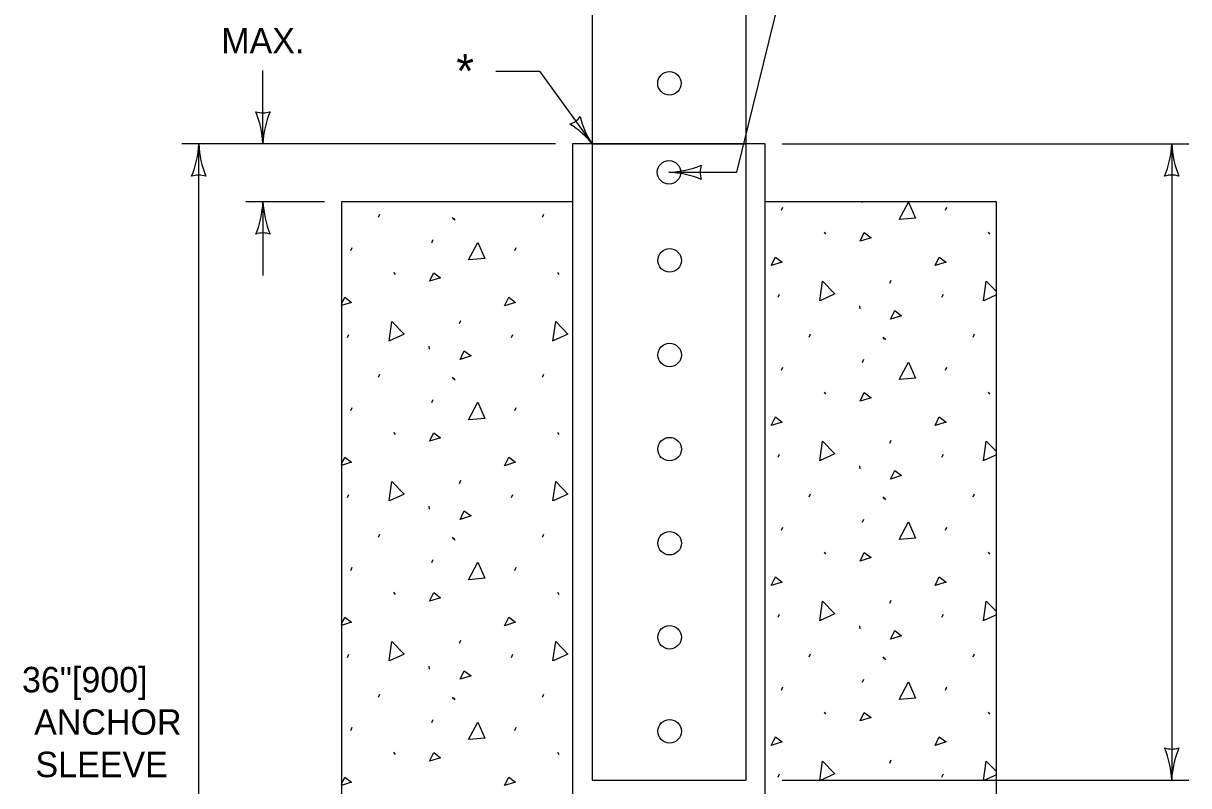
# Model space of a CAD drawing. Extents: x 49940 to 50043, y 49986 to 50011.
# Drawn here: x 50011.713 to 50014.462, y 49993.98 to 49995.777 of the extents above; entities that cross this region are included whole.
import ezdxf

# ---------------------------------------------------------------- set-up
doc = ezdxf.new("R2010")
doc.units = 0
for name, color, linetype in [('Level 1', 7, 'Continuous'), ('Level 2', 7, 'Continuous'), ('Level 3', 7, 'Continuous'), ('Level 4', 7, 'Continuous')]:
    doc.layers.add(name, color=color, linetype=linetype)

msp = doc.modelspace()

# ---------------------------------------------------------------- linework, layer by layer
at = {"layer": 'Level 1'}
for p, q in [((50013.4632, 49995.4928), (50013.0088, 49995.4928)), ((50013.0088, 49995.4928), (50013.0088, 49992.7712)), ((50013.4632, 49992.7712), (50013.4632, 49995.4928)), ((50013.0088, 49995.3565), (50012.4634, 49995.3565)), ((50012.4634, 49995.3565), (50012.4634, 49992.6303)), ((50014.0084, 49995.3565), (50013.4632, 49995.3565)), ((50013.6927, 49995.355), (50013.6934, 49995.3565)), ((50014.0084, 49992.6303), (50014.0084, 49995.3565)), ((50012.5512, 49995.3201), (50012.5544, 49995.3273)), ((50012.9377, 49995.3201), (50012.941, 49995.3273)), ((50013.5014, 49995.3365), (50013.5047, 49995.3437)), ((50013.888, 49995.3365), (50013.8912, 49995.3437)), ((50012.7247, 49995.3201), (50012.728, 49995.3151)), ((50012.728, 49995.3182), (50012.7313, 49995.3134)), ((50013.6024, 49995.2848), (50013.6055, 49995.28)), ((50013.9889, 49995.2848), (50013.992, 49995.28)), ((50012.4858, 49995.2416), (50012.4889, 49995.2489)), ((50012.677, 49995.2602), (50012.6802, 49995.2675)), ((50012.8724, 49995.2416), (50012.8756, 49995.2489)), ((50012.5866, 49995.1901), (50012.5899, 49995.1852)), ((50012.9732, 49995.1901), (50012.9764, 49995.1852)), ((50013.7573, 49995.1647), (50013.7605, 49995.1718)), ((50013.4934, 49995.1314), (50013.4966, 49995.1388)), ((50013.88, 49995.1314), (50013.8832, 49995.1388)), ((50013.6853, 49995.1112), (50013.686, 49995.104)), ((50012.7416, 49995.0697), (50012.7449, 49995.0771)), ((50012.4778, 49995.0366), (50012.481, 49995.044)), ((50012.8643, 49995.0366), (50012.8674, 49995.044)), ((50013.5668, 49995.0378), (50013.5701, 49995.0451)), ((50013.7404, 49995.0378), (50013.7435, 49995.0331)), ((50013.7435, 49995.036), (50013.7468, 49995.0311)), ((50013.9535, 49995.0378), (50013.9565, 49995.0451)), ((50012.6696, 49995.0164), (50012.6704, 49995.009)), ((50013.6927, 49994.9781), (50013.696, 49994.9853)), ((50012.5512, 49994.9431), (50012.5544, 49994.9504)), ((50012.7247, 49994.9431), (50012.728, 49994.9382)), ((50012.728, 49994.9411), (50012.7313, 49994.9364)), ((50012.9377, 49994.9431), (50012.941, 49994.9504)), ((50013.5014, 49994.9595), (50013.5047, 49994.9667)), ((50013.888, 49994.9595), (50013.8912, 49994.9667)), ((50012.677, 49994.8833), (50012.6802, 49994.8906)), ((50013.6024, 49994.9079), (50013.6055, 49994.903)), ((50013.9889, 49994.9079), (50013.992, 49994.903)), ((50012.4858, 49994.8648), (50012.4889, 49994.872)), ((50012.8724, 49994.8648), (50012.8756, 49994.872)), ((50012.5866, 49994.8131), (50012.5899, 49994.8082)), ((50012.9732, 49994.8131), (50012.9764, 49994.8082)), ((50013.7573, 49994.7876), (50013.7605, 49994.7948)), ((50013.4934, 49994.7545), (50013.4966, 49994.7617)), ((50013.88, 49994.7545), (50013.8832, 49994.7617)), ((50013.6853, 49994.7342), (50013.686, 49994.727)), ((50012.7416, 49994.6928), (50012.7449, 49994.7001)), ((50012.4778, 49994.6597), (50012.481, 49994.6669)), ((50012.8643, 49994.6597), (50012.8674, 49994.6669)), ((50013.5668, 49994.6609), (50013.5701, 49994.6681)), ((50013.9535, 49994.6609), (50013.9565, 49994.6681)), ((50012.6696, 49994.6395), (50012.6704, 49994.6322)), ((50013.7404, 49994.6609), (50013.7435, 49994.6561)), ((50013.7435, 49994.6591), (50013.7468, 49994.6543)), ((50013.5014, 49994.5826), (50013.5047, 49994.5898)), ((50013.6927, 49994.6011), (50013.696, 49994.6084)), ((50013.888, 49994.5826), (50013.8912, 49994.5898)), ((50012.5512, 49994.5661), (50012.5544, 49994.5733)), ((50012.7247, 49994.5661), (50012.728, 49994.5614)), ((50012.728, 49994.5643), (50012.7313, 49994.5594)), ((50012.9377, 49994.5661), (50012.941, 49994.5733)), ((50013.6024, 49994.531), (50013.6055, 49994.5261)), ((50013.9889, 49994.531), (50013.992, 49994.5261)), ((50012.677, 49994.5063), (50012.6802, 49994.5136)), ((50012.4858, 49994.4878), (50012.4889, 49994.495)), ((50012.8724, 49994.4878), (50012.8756, 49994.495)), ((50012.5866, 49994.4361), (50012.5899, 49994.4311)), ((50012.9732, 49994.4361), (50012.9764, 49994.4311)), ((50013.7573, 49994.4106), (50013.7605, 49994.4179)), ((50013.4934, 49994.3776), (50013.4966, 49994.3848)), ((50013.88, 49994.3776), (50013.8832, 49994.3848)), ((50013.6853, 49994.3573), (50013.686, 49994.3501)), ((50012.7416, 49994.3159), (50012.7449, 49994.3231)), ((50012.4778, 49994.2827), (50012.481, 49994.29)), ((50012.8643, 49994.2827), (50012.8674, 49994.29)), ((50013.5668, 49994.2839), (50013.5701, 49994.2912)), ((50013.7404, 49994.2839), (50013.7435, 49994.2791)), ((50013.7435, 49994.2821), (50013.7468, 49994.2773)), ((50013.9535, 49994.2839), (50013.9565, 49994.2912)), ((50012.6696, 49994.2624), (50012.6704, 49994.2553)), ((50013.6927, 49994.2241), (50013.696, 49994.2314)), ((50013.5014, 49994.2055), (50013.5047, 49994.213)), ((50013.888, 49994.2055), (50013.8912, 49994.213)), ((50012.5512, 49994.1892), (50012.5544, 49994.1964)), ((50012.7247, 49994.1892), (50012.728, 49994.1844)), ((50012.728, 49994.1873), (50012.7313, 49994.1825)), ((50012.9377, 49994.1892), (50012.941, 49994.1964)), ((50013.6024, 49994.1539), (50013.6055, 49994.1491)), ((50013.9889, 49994.1539), (50013.992, 49994.1491)), ((50012.4858, 49994.1108), (50012.4889, 49994.118)), ((50012.677, 49994.1293), (50012.6802, 49994.1367)), ((50012.8724, 49994.1108), (50012.8756, 49994.118)), ((50012.5866, 49994.0592), (50012.5899, 49994.0542)), ((50012.9732, 49994.0592), (50012.9764, 49994.0542)), ((50013.7573, 49994.0337), (50013.7605, 49994.041)), ((50013.4934, 49994.0006), (50013.4966, 49994.0079)), ((50013.88, 49994.0006), (50013.8832, 49994.0079))]:
    msp.add_line(p, q, dxfattribs=at)
for points in [[(50013.0548, 49996.3776), (50013.0548, 49995.493), (50013.4182, 49995.493), (50013.418, 49996.3777)], [(50013.7792, 49995.3148), (50013.8008, 49995.3559), (50013.8178, 49995.318), (50013.7799, 49995.3148)], [(50013.6872, 49995.2637), (50013.6967, 49995.284), (50013.7129, 49995.2719), (50013.6872, 49995.2637)], [(50012.7634, 49995.2199), (50012.7852, 49995.261), (50012.8021, 49995.2231), (50012.7642, 49995.2199)], [(50013.4774, 49995.2061), (50013.4871, 49995.2263), (50013.5032, 49995.2142), (50013.4774, 49995.2061)], [(50013.8639, 49995.2061), (50013.8736, 49995.2263), (50013.8898, 49995.2142), (50013.8639, 49995.2061)], [(50012.6714, 49995.1691), (50012.6812, 49995.1892), (50012.6974, 49995.1772), (50012.6714, 49995.1691)], [(50013.5917, 49995.1232), (50013.598, 49995.1693), (50013.6269, 49995.1394), (50013.5923, 49995.1234)], [(50013.9782, 49995.1232), (50013.9844, 49995.1693), (50014.0084, 49995.1448)], [(50014.0084, 49995.137), (50013.9789, 49995.1234)], [(50012.4634, 49995.1149), (50012.4715, 49995.1315), (50012.4876, 49995.1195), (50012.4634, 49995.1118)], [(50012.8485, 49995.1113), (50012.8581, 49995.1315), (50012.8741, 49995.1195), (50012.8485, 49995.1113)], [(50013.7589, 49995.0798), (50013.7686, 49995.1), (50013.7848, 49995.0879), (50013.7589, 49995.0798)], [(50012.5758, 49995.0282), (50012.5823, 49995.0744), (50012.6112, 49995.0447), (50012.5768, 49995.0287)], [(50012.9625, 49995.0282), (50012.969, 49995.0744), (50012.9979, 49995.0447), (50012.9633, 49995.0287)], [(50012.7432, 49994.9849), (50012.753, 49995.0053), (50012.7692, 49994.9931), (50012.7432, 49994.9849)], [(50013.7792, 49994.9378), (50013.8008, 49994.9789), (50013.8178, 49994.941), (50013.7799, 49994.9378)], [(50013.6872, 49994.8869), (50013.6967, 49994.9071), (50013.7129, 49994.8948), (50013.6872, 49994.8869)], [(50012.7634, 49994.8429), (50012.7852, 49994.884), (50012.8021, 49994.8461), (50012.7642, 49994.8429)], [(50013.4774, 49994.8292), (50013.4871, 49994.8495), (50013.5032, 49994.8372), (50013.4774, 49994.8292)], [(50013.8639, 49994.8292), (50013.8736, 49994.8495), (50013.8898, 49994.8372), (50013.8639, 49994.8292)], [(50012.6714, 49994.7921), (50012.6812, 49994.8121), (50012.6974, 49994.8002), (50012.6714, 49994.7921)], [(50013.5917, 49994.7461), (50013.598, 49994.7922), (50013.6269, 49994.7625), (50013.5923, 49994.7464)], [(50013.9782, 49994.7461), (50013.9844, 49994.7922), (50014.0084, 49994.7677)], [(50012.4634, 49994.7379), (50012.4715, 49994.7546), (50012.4876, 49994.7425), (50012.4634, 49994.7349)], [(50012.8485, 49994.7345), (50012.8581, 49994.7546), (50012.8741, 49994.7425), (50012.8485, 49994.7345)], [(50014.0084, 49994.7601), (50013.9789, 49994.7464)], [(50013.7589, 49994.7028), (50013.7686, 49994.7231), (50013.7848, 49994.7111), (50013.7589, 49994.7028)], [(50012.5758, 49994.6514), (50012.5823, 49994.6975), (50012.6112, 49994.6677), (50012.5768, 49994.6517)], [(50012.9625, 49994.6514), (50012.969, 49994.6975), (50012.9979, 49994.6677), (50012.9633, 49994.6517)], [(50012.7432, 49994.6081), (50012.753, 49994.6282), (50012.7692, 49994.6162), (50012.7432, 49994.6081)], [(50013.7792, 49994.5608), (50013.8008, 49994.6019), (50013.8178, 49994.564), (50013.7799, 49994.5608)], [(50013.6872, 49994.5099), (50013.6967, 49994.5301), (50013.7129, 49994.5179), (50013.6872, 49994.5099)], [(50012.7634, 49994.4659), (50012.7852, 49994.5071), (50012.8021, 49994.4692), (50012.7642, 49994.4659)], [(50013.4774, 49994.4523), (50013.4871, 49994.4724), (50013.5032, 49994.4603), (50013.4774, 49994.4523)], [(50013.8639, 49994.4523), (50013.8736, 49994.4724), (50013.8898, 49994.4603), (50013.8639, 49994.4523)], [(50012.6714, 49994.415), (50012.6812, 49994.4353), (50012.6974, 49994.4232), (50012.6714, 49994.415)], [(50013.5917, 49994.3692), (50013.598, 49994.4154), (50013.6269, 49994.3854), (50013.5923, 49994.3695)], [(50013.9782, 49994.3692), (50013.9844, 49994.4154), (50014.0084, 49994.3908)], [(50012.4634, 49994.3608), (50012.4715, 49994.3776), (50012.4876, 49994.3655), (50012.4634, 49994.3578)], [(50012.8485, 49994.3573), (50012.8581, 49994.3776), (50012.8741, 49994.3655), (50012.8485, 49994.3573)], [(50014.0084, 49994.3831), (50013.9789, 49994.3695)], [(50013.7589, 49994.3259), (50013.7686, 49994.3461), (50013.7848, 49994.3339), (50013.7589, 49994.3259)], [(50012.5758, 49994.2745), (50012.5823, 49994.3205), (50012.6112, 49994.2907), (50012.5768, 49994.2746)], [(50012.9625, 49994.2745), (50012.969, 49994.3205), (50012.9979, 49994.2907), (50012.9633, 49994.2746)], [(50012.7432, 49994.2311), (50012.753, 49994.2512), (50012.7692, 49994.2393), (50012.7432, 49994.2311)], [(50013.7792, 49994.1838), (50013.8008, 49994.2249), (50013.8178, 49994.1869), (50013.7799, 49994.1838)], [(50013.6872, 49994.1329), (50013.6967, 49994.1531), (50013.7129, 49994.1411), (50013.6872, 49994.1329)], [(50012.7634, 49994.0891), (50012.7852, 49994.1301), (50012.8021, 49994.0923), (50012.7642, 49994.0891)], [(50013.4774, 49994.0752), (50013.4871, 49994.0955), (50013.5032, 49994.0834), (50013.4774, 49994.0752)], [(50013.8639, 49994.0752), (50013.8736, 49994.0955), (50013.8898, 49994.0834), (50013.8639, 49994.0752)], [(50012.6714, 49994.0381), (50012.6812, 49994.0584), (50012.6974, 49994.0461), (50012.6714, 49994.0381)], [(50013.5917, 49993.9923), (50013.598, 49994.0385), (50013.6269, 49994.0084), (50013.5923, 49993.9925)], [(50013.9782, 49993.9923), (50013.9844, 49994.0385), (50014.0084, 49994.0138)], [(50012.4634, 49993.9839), (50012.4715, 49994.0006), (50012.4876, 49993.9885), (50012.4634, 49993.9811)], [(50012.8485, 49993.9804), (50012.8581, 49994.0006), (50012.8741, 49993.9885), (50012.8485, 49993.9804)], [(50014.0084, 49994.0061), (50013.9789, 49993.9925)]]:
    msp.add_lwpolyline(points, dxfattribs=at)
for centre in [(50013.2371, 49995.6358), (50013.2361, 49995.426), (50013.2376, 49995.2184), (50013.2376, 49994.9954), (50013.2376, 49994.7736), (50013.2376, 49994.5519), (50013.2376, 49994.3302), (50013.2376, 49994.1085)]:
    msp.add_circle(centre, 0.0277, dxfattribs=at)
at = {"layer": 'Level 3'}
for p, q in [((50013.3963, 49995.426), (50013.6761, 49996.5696)), ((50012.2784, 49995.4928), (50012.2784, 49995.6663)), ((50012.8273, 49995.6648), (50012.9306, 49995.6648)), ((50012.9306, 49995.6648), (50013.0548, 49995.493)), ((50012.9688, 49995.4928), (50012.0869, 49995.4928)), ((50012.1269, 49992.7712), (50012.1269, 49995.4928)), ((50013.5032, 49995.493), (50014.4619, 49995.493)), ((50014.4219, 49995.493), (50014.4219, 49993.9934)), ((50013.2361, 49995.426), (50013.3963, 49995.426)), ((50012.4234, 49995.3565), (50012.2384, 49995.3565)), ((50012.2784, 49995.3565), (50012.2784, 49995.1831)), ((50013.5032, 49993.9934), (50014.4619, 49993.9934))]:
    msp.add_line(p, q, dxfattribs=at)
for centre, radius, start, end in [((50012.2784, 49995.621), 0.0548, 252.1388, 287.8612), ((50012.0457, 49995.4813), 0.233, 2.8273, 22.0772), ((50012.5005, 49995.4837), 0.2223, 157.456, 177.6395), ((50012.9872, 49995.5865), 0.0493, 288.0017, 323.724), ((50013.2216, 49995.6035), 0.2001, 193.3189, 213.5024), ((50012.8911, 49995.3619), 0.2097, 38.6902, 57.94), ((50011.9048, 49995.502), 0.2223, 337.456, 357.6395), ((50012.3596, 49995.5043), 0.233, 182.8273, 202.0772), ((50014.1998, 49995.5022), 0.2223, 337.456, 357.6395), ((50014.6546, 49995.5045), 0.233, 182.8273, 202.0772), ((50013.2246, 49995.6587), 0.233, 272.8273, 292.0772), ((50013.3643, 49995.426), 0.0548, 162.1388, 197.8612), ((50012.1269, 49995.3646), 0.0548, 72.1388, 107.8612), ((50013.2269, 49995.2039), 0.2223, 67.456, 87.6395), ((50014.4219, 49995.3648), 0.0548, 72.1388, 107.8612), ((50012.0563, 49995.3657), 0.2223, 337.456, 357.6395), ((50012.5111, 49995.368), 0.233, 182.8273, 202.0772), ((50012.2784, 49995.2283), 0.0548, 72.1388, 107.8612), ((50014.4219, 49994.1216), 0.0548, 252.1388, 287.8612), ((50014.1892, 49993.9819), 0.233, 2.8273, 22.0772), ((50014.644, 49993.9843), 0.2223, 157.456, 177.6395)]:
    msp.add_arc(centre, radius, start, end, dxfattribs=at)
at = {"layer": 'Level 4'}
for p, q in [((50013.0548, 49995.493), (50013.0548, 49993.9934)), ((50013.4182, 49993.9934), (50013.4182, 49995.493)), ((50013.0548, 49993.9934), (50013.4182, 49993.9934))]:
    msp.add_line(p, q, dxfattribs=at)

# ---------------------------------------------------------------- texts
at = {"layer": 'Level 2'}
for s, p in [('MAX.', (50012.1801, 49995.7063)), ('36"[900]', (50011.7101, 49994.2004)), ('ANCHOR', (50011.7387, 49994.1004)), ('SLEEVE', (50011.7418, 49994.0004))]:
    msp.add_text(s, height=0.06, dxfattribs=at).set_placement(p)
msp.add_text('*', height=0.08, rotation=359.5, dxfattribs=at).set_placement((50012.7339, 49995.6253))

doc.saveas('drawing.dxf')
